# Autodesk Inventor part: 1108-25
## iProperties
Created: 2007-03
Part Number: 1108-25
Document SubType Name: Modeling
Designer: Andy Moles
Material: Steel
Mass: 0.254649 g
Surface Area: 1.23838 cm^2
Volume: 0.0324394 cm^3
Density: 7.85 g/cm^3
Author: Andy Moles
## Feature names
1. Base1
